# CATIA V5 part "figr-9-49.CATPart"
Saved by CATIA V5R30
Part number: Part1
Bounding box of the stored display mesh (mm): x -53.48 to 62.241, y -50 to 50, z -57.709 to 133.109
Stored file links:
  D:\PROJECTS\CATIA V56R 2020\Resources\Parts File\c09_catia_v5_6r2020_prt\figr-9-49.CATPart
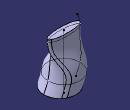
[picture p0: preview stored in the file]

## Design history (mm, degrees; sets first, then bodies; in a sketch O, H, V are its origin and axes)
Body1 (main body)
  Plane1: type Offset, RefPlane xy-plane, Offset 103
  Sketch1 on Plane1, origin (0, 0, 103), H (1, 0, 0), V (0, 1, 0)
    ellipse A1 centre (0, 0) semi-axes 50, 13.2069 rotation 0
    point P1 (50, 0)
    "Radius" A1 = 50
    coincidence: P1 H, A1 P1
  Extremum1: Reference Sketch1, Direction (1, 2, 3)
  Sketch2 on xy-plane, origin (0, 0, 0), H (1, 0, 0), V (0, 1, 0)
    circle A1 centre (0, 0) radius 50
    radius A1 = 50
  Extremum2: Reference Sketch2, Direction (1, 2, 3)
  Sketch3 on zx-plane, origin (0, 0, 0), H (-1, 0, 0), V (0, 0, 1)
    spline S1 through (37.7591, -31.0289) (41.8235, -21.251) (50, 0) (49.8084, 85.7657) (50, 103) (41.6255, 133.1089)
    reference projected line E1 (-50, 103) -> (50, 103) from Sketch1.A1
    point P1 (50, 0)
    point P2 (50, 103)
    distance V P1 = 50
    distance P2 V = 50
    coincidence: P1 H, P2 E1
  Sketch4 on zx-plane, origin (0, 0, 0), H (-1, 0, 0), V (0, 0, 1)
    line L1 (0, 111.062) -> (0, -57.7094)
    point P1 (0, 111.062)
    coincidence: P1 V
    vertical: L1 V
  Loft1: solid, Sections (Sketch1; Sketch2), Spine Sketch4, Guides Sketch3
